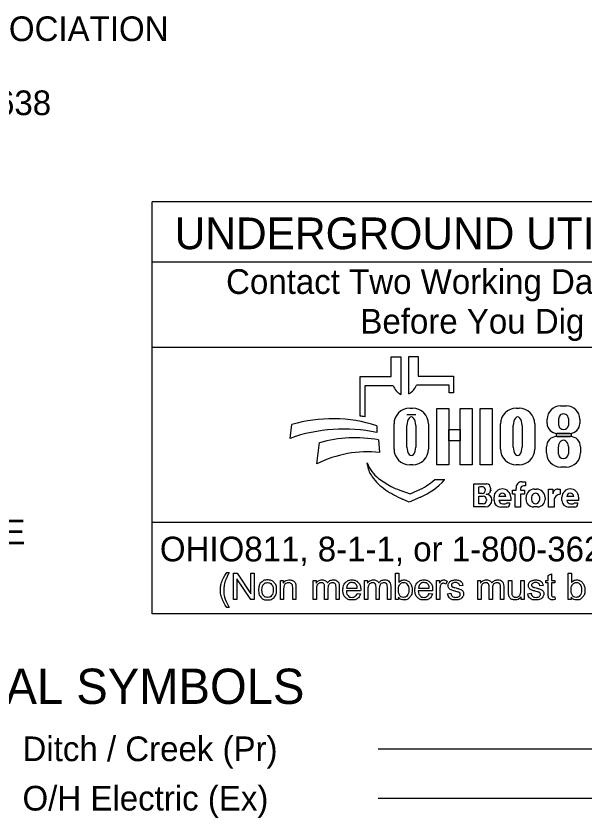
# Model space of a CAD drawing. Extents: x 0 to 34, y 0 to 22.
# Drawn here: x 7.923 to 11.147, y 5.615 to 10.163 of the extents above; entities that cross this region are included whole.
import ezdxf

# ---------------------------------------------------------------- set-up
doc = ezdxf.new("R2010")
doc.units = 0
for name, color, linetype in [('SH_Data', 7, 'Continuous'), ('SH_Text', 7, 'Continuous'), ('UT_X_Overhead_Electric', 7, 'Continuous')]:
    doc.layers.add(name, color=color, linetype=linetype)

msp = doc.modelspace()

# ---------------------------------------------------------------- linework, layer by layer
at = {"layer": 'SH_Data'}
for p, q in [((8.6934, 6.7724), (8.6934, 9.1099)), ((12.9434, 9.1099), (8.6934, 9.1099)), ((8.6934, 8.7683), (12.9434, 8.7683)), ((8.6934, 8.2849), (12.9434, 8.2849)), ((12.9434, 7.2902), (8.6934, 7.2902)), ((12.9434, 6.7724), (8.6934, 6.7724))]:
    msp.add_line(p, q, dxfattribs=at)
at = {"layer": 'SH_Text'}
for p, q in [((10.1488, 8.0196), (10.1488, 8.2317)), ((10.1488, 8.2317), (10.2024, 8.2317)), ((10.2024, 8.2317), (10.2024, 8.1202)), ((10.0495, 8.1179), (10.0495, 8.2294)), ((10.0495, 8.2294), (10.1031, 8.2294)), ((10.1031, 8.2294), (10.1031, 8.0173)), ((9.8735, 7.894), (9.8735, 8.1179)), ((9.8735, 8.1179), (10.0495, 8.1179)), ((10.2024, 8.1202), (10.4017, 8.1202)), ((10.4017, 8.1202), (10.4017, 8.0264)), ((9.8987, 8.0664), (9.8987, 7.8896)), ((10.0599, 8.0664), (9.8987, 8.0664)), ((10.3784, 8.0687), (10.192, 8.0687)), ((10.3784, 8.0264), (10.3784, 8.0687)), ((10.4017, 8.0264), (10.3784, 8.0264)), ((10.1544, 7.9387), (10.171, 7.9387)), ((10.7575, 7.9387), (10.774, 7.9387)), ((11.009, 7.9527), (11.0418, 7.9527)), ((10.1877, 7.9017), (10.1379, 7.9017)), ((10.9327, 7.8521), (10.9327, 7.8764)), ((10.9989, 7.8407), (10.9989, 7.88)), ((11.053, 7.88), (11.053, 7.8407)), ((11.1181, 7.8764), (11.1181, 7.8521)), ((9.4761, 7.7677), (9.4855, 7.8458)), ((9.9668, 7.8393), (9.9668, 7.8005)), ((10.065, 7.7072), (10.065, 7.8492)), ((10.1379, 7.7186), (10.1379, 7.8409)), ((10.1877, 7.8409), (10.1877, 7.7186)), ((10.2604, 7.8492), (10.2604, 7.7072)), ((10.668, 7.7072), (10.668, 7.8492)), ((10.7409, 7.7186), (10.7409, 7.8409)), ((10.7907, 7.8409), (10.7907, 7.7186)), ((10.8635, 7.8492), (10.8635, 7.7072)), ((10.9869, 7.7778), (11.0642, 7.7778)), ((11.0621, 7.7961), (10.9887, 7.7961)), ((9.628, 7.6231), (9.6426, 7.7433)), ((9.9768, 7.7587), (9.983, 7.6878)), ((10.929, 7.6859), (10.929, 7.7199)), ((10.9965, 7.6799), (10.9965, 7.7208)), ((11.0534, 7.7208), (11.0534, 7.6799)), ((11.1221, 7.7199), (11.1221, 7.6859)), ((9.9156, 7.6102), (9.9126, 7.6282)), ((10.171, 7.6177), (10.1544, 7.6177)), ((10.774, 7.6177), (10.7575, 7.6177)), ((11.0412, 7.6049), (11.01, 7.6049)), ((10.2959, 7.5344), (10.3534, 7.5344)), ((10.5172, 7.3786), (10.5172, 7.5093)), ((10.5172, 7.5093), (10.5884, 7.5093)), ((10.7898, 7.5221), (10.8093, 7.5221)), ((10.8093, 7.5221), (10.8093, 7.4992)), ((10.0975, 7.474), (10.1569, 7.4535)), ((10.1569, 7.4535), (10.198, 7.4713)), ((10.5452, 7.4559), (10.5452, 7.4928)), ((10.5704, 7.4928), (10.5491, 7.4928)), ((10.6122, 7.4856), (10.6122, 7.4777)), ((10.7372, 7.4508), (10.7372, 7.4737)), ((10.7372, 7.4737), (10.7565, 7.4737)), ((10.7565, 7.4737), (10.7565, 7.4842)), ((10.7826, 7.4822), (10.7826, 7.4737)), ((10.7826, 7.4737), (10.8042, 7.4737)), ((10.8093, 7.4987), (10.7991, 7.4987)), ((10.8042, 7.4737), (10.8042, 7.4508)), ((10.861, 7.4803), (10.8732, 7.4803)), ((10.9413, 7.3774), (10.9413, 7.4801)), ((10.9413, 7.4801), (10.9658, 7.4801)), ((10.9658, 7.4801), (10.9658, 7.4532)), ((10.9931, 7.4801), (11.007, 7.4801)), ((11.007, 7.4801), (11.007, 7.4505)), ((10.1509, 7.4065), (10.1136, 7.4229)), ((10.2142, 7.4339), (10.1509, 7.4065)), ((10.5646, 7.4559), (10.5452, 7.4559)), ((10.5452, 7.3964), (10.5452, 7.4393)), ((10.5452, 7.4393), (10.5707, 7.4393)), ((10.5889, 7.4212), (10.5889, 7.4148)), ((10.6202, 7.4183), (10.6202, 7.4179)), ((10.6318, 7.4154), (10.6318, 7.4338)), ((10.6984, 7.4378), (10.6598, 7.4378)), ((10.7263, 7.4161), (10.6599, 7.4161)), ((10.7263, 7.4338), (10.7263, 7.4161)), ((10.7521, 7.4508), (10.7372, 7.4508)), ((10.7521, 7.3774), (10.7521, 7.4508)), ((10.8042, 7.4508), (10.7826, 7.4508)), ((10.7826, 7.4508), (10.7826, 7.3774)), ((10.8132, 7.4217), (10.8132, 7.4325)), ((10.921, 7.4325), (10.921, 7.4217)), ((10.9718, 7.4155), (10.9718, 7.3774)), ((11.0167, 7.4154), (11.0167, 7.4338)), ((11.0833, 7.4378), (11.0448, 7.4378)), ((11.1112, 7.4161), (11.0448, 7.4161)), ((11.1112, 7.4338), (11.1112, 7.4161)), ((10.5809, 7.3786), (10.5172, 7.3786)), ((10.5705, 7.3964), (10.5452, 7.3964)), ((10.7051, 7.3774), (10.6697, 7.3774)), ((10.6808, 7.3969), (10.6949, 7.3969)), ((10.7035, 7.4025), (10.7204, 7.4025)), ((10.7204, 7.4025), (10.7204, 7.3926)), ((10.7826, 7.3774), (10.7521, 7.3774)), ((10.8782, 7.3789), (10.856, 7.3789)), ((10.9718, 7.3774), (10.9413, 7.3774)), ((11.0901, 7.3774), (11.0547, 7.3774)), ((11.0657, 7.3969), (11.0799, 7.3969)), ((11.0884, 7.4025), (11.1053, 7.4025)), ((11.1053, 7.4025), (11.1053, 7.3926)), ((9.9753, 6.0072), (13.8753, 6.0072))]:
    msp.add_line(p, q, dxfattribs=at)
for points in [[(10.3069, 7.9376), (10.3748, 7.9376), (10.3748, 7.6177), (10.3069, 7.6177)], [(10.439, 7.9376), (10.507, 7.9376), (10.507, 7.6177), (10.439, 7.6177)], [(10.5523, 7.9376), (10.6211, 7.9376), (10.6211, 7.6177), (10.5523, 7.6177)], [(10.3748, 7.8177), (10.439, 7.8177), (10.439, 7.7538), (10.3748, 7.7538)], [(10.9866, 7.7961), (11.0682, 7.7961), (11.0682, 7.7776), (10.9866, 7.7776)]]:
    msp.add_lwpolyline(points, close=True, dxfattribs=at)
for points in [[(9.118, 7.0062), (9.1312, 7.0062)], [(9.1548, 6.8535), (9.1548, 7.0036), (9.1751, 7.0036), (9.2541, 6.8857), (9.2541, 7.0036), (9.2731, 7.0036), (9.2731, 6.8535), (9.2528, 6.8535), (9.1738, 6.9714), (9.1738, 6.8535), (9.1548, 6.8535)], [(10.0902, 6.8535), (10.0732, 6.8535), (10.0732, 7.0036), (10.0916, 7.0036), (10.0916, 6.9501)], [(11.0693, 6.8535), (11.0523, 6.8535), (11.0523, 7.0036), (11.0707, 7.0036), (11.0707, 6.9501)], [(9.4207, 6.8535), (9.4207, 6.9623), (9.4373, 6.9623), (9.4373, 6.9469)], [(9.6072, 6.8535), (9.6072, 6.9623), (9.6236, 6.9623), (9.6236, 6.947)], [(9.8985, 6.8535), (9.8985, 6.9623), (9.915, 6.9623), (9.915, 6.947)], [(10.3063, 6.8535), (10.3063, 6.9623), (10.3229, 6.9623), (10.3229, 6.9458)], [(10.3654, 6.9588), (10.3589, 6.9418)], [(10.5395, 6.8535), (10.5395, 6.9623), (10.556, 6.9623), (10.556, 6.947)], [(10.7138, 6.8949), (10.7138, 6.9623), (10.7323, 6.9623), (10.7323, 6.902)], [(10.7835, 6.9041), (10.7835, 6.9623), (10.802, 6.9623), (10.802, 6.8535), (10.7855, 6.8535)], [(10.9392, 6.8853), (10.9392, 6.948), (10.9256, 6.948), (10.9256, 6.9623), (10.9392, 6.9623), (10.9392, 6.9893), (10.9576, 7.0003), (10.9576, 6.9623), (10.976, 6.9623), (10.976, 6.948), (10.9576, 6.948), (10.9576, 6.8843)], [(9.4392, 6.9129), (9.4392, 6.8535), (9.4207, 6.8535)], [(9.5091, 6.9204), (9.5091, 6.8535), (9.4907, 6.8535), (9.4907, 6.9196)], [(9.6902, 6.9167), (9.6902, 6.8535), (9.6718, 6.8535), (9.6718, 6.9241)], [(9.7547, 6.9282), (9.7547, 6.8535), (9.7362, 6.8535), (9.7362, 6.922)], [(9.7958, 6.9183), (9.8565, 6.9183)], [(9.9816, 6.9167), (9.9816, 6.8535), (9.9632, 6.8535), (9.9632, 6.9241)], [(10.046, 6.9282), (10.046, 6.8535), (10.0276, 6.8535), (10.0276, 6.922)], [(10.2038, 6.9183), (10.2645, 6.9183)], [(10.4553, 6.9342), (10.4372, 6.9318)], [(10.6226, 6.9167), (10.6226, 6.8535), (10.6042, 6.8535), (10.6042, 6.9241)], [(10.687, 6.9282), (10.687, 6.8535), (10.6686, 6.8535), (10.6686, 6.922)], [(10.9099, 6.9342), (10.8918, 6.9318)], [(9.6256, 6.9099), (9.6256, 6.8535), (9.6072, 6.8535)], [(9.8759, 6.9032), (9.7947, 6.9032)], [(9.8563, 6.8886), (9.8754, 6.8862)], [(9.917, 6.9099), (9.917, 6.8535), (9.8985, 6.8535)], [(10.0902, 6.8671), (10.0902, 6.8535)], [(10.2839, 6.9032), (10.2027, 6.9032)], [(10.2643, 6.8886), (10.2834, 6.8862)], [(10.3247, 6.9105), (10.3247, 6.8535), (10.3063, 6.8535)], [(10.3689, 6.886), (10.3871, 6.8889)], [(10.558, 6.9099), (10.558, 6.8535), (10.5395, 6.8535)], [(10.7855, 6.8535), (10.7855, 6.8696)], [(10.8235, 6.886), (10.8417, 6.8889)], [(10.976, 6.8699), (10.9787, 6.8536)], [(11.0693, 6.8671), (11.0693, 6.8535)], [(9.1312, 6.8093), (9.118, 6.8093)]]:
    msp.add_lwpolyline(points, dxfattribs=at)
for centre, radius, start, end in [((10.1512, 8.1032), 0.0985, 201.9296, 240.7469), ((10.1006, 8.1055), 0.0985, 299.2531, 338.0704), ((10.1544, 7.8492), 0.0895, 90, 180), ((10.171, 7.8492), 0.0895, 0, 90), ((10.7575, 7.8492), 0.0895, 90, 180), ((10.774, 7.8492), 0.0895, 0, 90), ((11.009, 7.8764), 0.0763, 90, 180), ((11.0418, 7.8764), 0.0763, 0, 90), ((9.7156, 7.0597), 0.8191, 72.1402, 106.3144), ((9.7454, 7.085), 0.8191, 79.2074, 81.0007), ((10.9887, 7.8521), 0.056, 180, 270), ((11.0621, 7.8521), 0.056, 270, 0), ((9.7787, 6.9286), 0.8919, 77.8238, 109.8274), ((10.9869, 7.7199), 0.0579, 90, 180), ((11.0642, 7.7199), 0.0579, 0, 90), ((9.8426, 7.0389), 0.7322, 79.44, 105.8467), ((9.9146, 7.0557), 0.6357, 83.8248, 116.8021), ((10.1544, 7.7072), 0.0895, 180, 270), ((10.171, 7.7072), 0.0895, 270, 0), ((10.7575, 7.7072), 0.0895, 180, 270), ((10.774, 7.7072), 0.0895, 270, 0), ((11.01, 7.6859), 0.081, 180, 270), ((11.0412, 7.6859), 0.081, 270, 0), ((10.1, 7.7003), 0.2008, 201.0457, 232.5314), ((10.0569, 7.6344), 0.1433, 189.6817, 216.0884), ((10.1906, 7.7318), 0.3088, 216.0884, 235.7167), ((10.2925, 7.9515), 0.5173, 232.5314, 241.794), ((10.0546, 7.8018), 0.3602, 293.4582, 312.0712), ((10.0546, 7.8018), 0.401, 293.4582, 317.8286), ((10.5884, 7.4856), 0.0238, 0, 90), ((10.7898, 7.4886), 0.0335, 90, 187.5187), ((10.3571, 7.976), 0.6044, 235.7167, 246.2325), ((10.2073, 7.7927), 0.3371, 241.794, 250.9821), ((10.5646, 7.4746), 0.0187, 270, 2.0582), ((10.5665, 7.4759), 0.0169, 357.8325, 90), ((10.588, 7.4749), 0.0243, 270, 6.6529), ((10.5986, 7.4734), 0.0175, 347.4023, 0), ((10.679, 7.4338), 0.0473, 0, 180), ((10.7991, 7.4822), 0.0165, 90, 180), ((10.861, 7.4325), 0.0478, 90, 180), ((10.8732, 7.4325), 0.0478, 0, 90), ((10.9927, 7.4532), 0.0269, 89.2449, 180), ((11.064, 7.4338), 0.0473, 0, 180), ((10.5705, 7.4148), 0.0184, 270, 0), ((10.5707, 7.4212), 0.0181, 0, 90), ((10.5809, 7.4179), 0.0393, 270, 0), ((10.5881, 7.4185), 0.0321, 4.0748, 90), ((10.5873, 7.4183), 0.033, 0, 11.7502), ((10.6697, 7.4154), 0.038, 180, 270), ((10.6791, 7.4368), 0.0193, 2.9632, 177.0368), ((10.6808, 7.4179), 0.021, 184.827, 270), ((10.856, 7.4217), 0.0428, 180, 270), ((10.8782, 7.4217), 0.0428, 270, 0), ((11.0067, 7.4155), 0.0349, 89.6033, 180), ((11.0547, 7.4154), 0.038, 180, 270), ((11.064, 7.4368), 0.0193, 2.9632, 177.0368), ((11.0657, 7.4179), 0.021, 184.827, 270), ((10.6949, 7.4063), 0.00938, 270, 335.9979), ((10.7051, 7.3926), 0.0152, 270, 0), ((11.0799, 7.4063), 0.00938, 270, 335.9979), ((11.0901, 7.3926), 0.0152, 270, 0)]:
    msp.add_arc(centre, radius, start, end, dxfattribs=at)
for centre, major_axis, ratio, start_param, end_param in [((10.1628, 7.8409), (0, 0.0484), 0.514403, 4.712389, 7.853982), ((10.7658, 7.8409), (0, 0.0484), 0.514403, 4.712389, 7.853982), ((11.0259, 7.88), (0.0271, 0), 0.969373, 0, 3.141593), ((11.0259, 7.8407), (0.0271, 0), 0.818453, 3.141593, 6.283185), ((11.0249, 7.7208), (0, 0.0358), 0.794529, 4.712389, 7.853982), ((10.1628, 7.7186), (0, 0.0484), 0.514403, 1.570796, 4.712389), ((10.7658, 7.7186), (0, 0.0484), 0.514403, 1.570796, 4.712389), ((11.0249, 7.6799), (0.0284, 0), 0.959837, 3.141593, 6.283185), ((10.8676, 7.4271), (0, 0.029), 0.832186, 4.712389, 7.853982), ((10.8676, 7.4271), (0, 0.0302), 0.797287, 1.570796, 4.712389)]:
    msp.add_ellipse(centre, major_axis=major_axis, ratio=ratio, start_param=start_param, end_param=end_param, dxfattribs=at)
for points in [[(9.118, 6.8093), (9.1028, 6.8286), (9.0922, 6.8544), (9.0816, 6.8802), (9.0816, 6.9078), (9.0816, 6.9322), (9.0895, 6.9545), (9.0988, 6.9805), (9.118, 7.0062)], [(9.1312, 7.0062), (9.1188, 6.9849), (9.1149, 6.9757), (9.1086, 6.9616), (9.105, 6.9462), (9.1006, 6.9271), (9.1006, 6.9077), (9.1006, 6.8585), (9.1312, 6.8093)], [(9.2973, 6.9079), (9.2973, 6.9381), (9.314, 6.9526), (9.3281, 6.9647), (9.3482, 6.9647), (9.3707, 6.9647), (9.3849, 6.95), (9.3991, 6.9353), (9.3991, 6.9094), (9.3991, 6.8885), (9.3928, 6.8764), (9.3865, 6.8644), (9.3745, 6.8577), (9.3625, 6.8511), (9.3482, 6.8511), (9.3254, 6.8511), (9.3113, 6.8657), (9.2973, 6.8804), (9.2973, 6.9079)], [(9.4373, 6.9469), (9.4493, 6.9647), (9.4719, 6.9647), (9.4818, 6.9647), (9.49, 6.9612), (9.4982, 6.9577), (9.5023, 6.9519), (9.5064, 6.9462), (9.5081, 6.9383), (9.5091, 6.9332), (9.5091, 6.9204)], [(9.6236, 6.947), (9.6288, 6.955), (9.6373, 6.9599), (9.6458, 6.9647), (9.6566, 6.9647), (9.6687, 6.9647), (9.6765, 6.9597), (9.6842, 6.9547), (9.6874, 6.9456), (9.7003, 6.9647), (9.721, 6.9647), (9.7372, 6.9647), (9.746, 6.9558), (9.7547, 6.9468), (9.7547, 6.9282)], [(9.8754, 6.8862), (9.8709, 6.8695), (9.8587, 6.8603), (9.8465, 6.8511), (9.8276, 6.8511), (9.8037, 6.8511), (9.7897, 6.8658), (9.7757, 6.8805), (9.7757, 6.907), (9.7757, 6.9344), (9.7899, 6.9496), (9.804, 6.9647), (9.8265, 6.9647), (9.8484, 6.9647), (9.8622, 6.9499), (9.876, 6.935), (9.876, 6.9081), (9.876, 6.9064), (9.8759, 6.9032)], [(9.915, 6.947), (9.9201, 6.955), (9.9286, 6.9599), (9.9371, 6.9647), (9.948, 6.9647), (9.9601, 6.9647), (9.9678, 6.9597), (9.9756, 6.9547), (9.9787, 6.9456), (9.9917, 6.9647), (10.0124, 6.9647), (10.0286, 6.9647), (10.0373, 6.9558), (10.046, 6.9468), (10.046, 6.9282)], [(10.0916, 6.9501), (10.1033, 6.9647), (10.1214, 6.9647), (10.1314, 6.9647), (10.1404, 6.9607), (10.1494, 6.9566), (10.1552, 6.9493), (10.1609, 6.942), (10.1642, 6.9317), (10.1675, 6.9213), (10.1675, 6.9095), (10.1675, 6.8816), (10.1537, 6.8663), (10.1398, 6.8511), (10.1205, 6.8511), (10.1012, 6.8511), (10.0902, 6.8671)], [(10.2834, 6.8862), (10.2789, 6.8695), (10.2667, 6.8603), (10.2545, 6.8511), (10.2356, 6.8511), (10.2117, 6.8511), (10.1977, 6.8658), (10.1837, 6.8805), (10.1837, 6.907), (10.1837, 6.9344), (10.1979, 6.9496), (10.212, 6.9647), (10.2345, 6.9647), (10.2563, 6.9647), (10.2702, 6.9499), (10.284, 6.935), (10.284, 6.9081), (10.284, 6.9064), (10.2839, 6.9032)], [(10.3229, 6.9458), (10.3292, 6.9574), (10.3346, 6.9611), (10.34, 6.9647), (10.3464, 6.9647), (10.3557, 6.9647), (10.3654, 6.9588)], [(10.3871, 6.8889), (10.3886, 6.8779), (10.3957, 6.872), (10.4027, 6.8662), (10.4154, 6.8662), (10.4281, 6.8662), (10.4343, 6.8714), (10.4404, 6.8766), (10.4404, 6.8835), (10.4404, 6.8898), (10.435, 6.8934), (10.4312, 6.8958), (10.4161, 6.8996), (10.3958, 6.9048), (10.388, 6.9085), (10.3801, 6.9122), (10.3761, 6.9188), (10.372, 6.9254), (10.372, 6.9334), (10.372, 6.9407), (10.3753, 6.9469), (10.3787, 6.9531), (10.3844, 6.9572), (10.3887, 6.9603), (10.3962, 6.9625), (10.4036, 6.9647), (10.4121, 6.9647), (10.4249, 6.9647), (10.4346, 6.961), (10.4443, 6.9573), (10.449, 6.951), (10.4536, 6.9447), (10.4553, 6.9342)], [(10.556, 6.947), (10.5611, 6.955), (10.5696, 6.9599), (10.5781, 6.9647), (10.589, 6.9647), (10.6011, 6.9647), (10.6088, 6.9597), (10.6166, 6.9547), (10.6197, 6.9456), (10.6327, 6.9647), (10.6534, 6.9647), (10.6696, 6.9647), (10.6783, 6.9558), (10.687, 6.9468), (10.687, 6.9282)], [(10.8417, 6.8889), (10.8432, 6.8779), (10.8503, 6.872), (10.8573, 6.8662), (10.8699, 6.8662), (10.8827, 6.8662), (10.8888, 6.8714), (10.895, 6.8766), (10.895, 6.8835), (10.895, 6.8898), (10.8896, 6.8934), (10.8858, 6.8958), (10.8707, 6.8996), (10.8504, 6.9048), (10.8425, 6.9085), (10.8347, 6.9122), (10.8306, 6.9188), (10.8266, 6.9254), (10.8266, 6.9334), (10.8266, 6.9407), (10.8299, 6.9469), (10.8332, 6.9531), (10.839, 6.9572), (10.8433, 6.9603), (10.8507, 6.9625), (10.8582, 6.9647), (10.8667, 6.9647), (10.8795, 6.9647), (10.8892, 6.961), (10.8989, 6.9573), (10.9035, 6.951), (10.9081, 6.9447), (10.9099, 6.9342)], [(11.0707, 6.9501), (11.0824, 6.9647), (11.1005, 6.9647), (11.1105, 6.9647), (11.1195, 6.9607), (11.1284, 6.9566), (11.1342, 6.9493), (11.14, 6.942), (11.1433, 6.9317), (11.1466, 6.9213), (11.1466, 6.9095), (11.1466, 6.8816), (11.1327, 6.8663), (11.1189, 6.8511), (11.0995, 6.8511), (11.0803, 6.8511), (11.0693, 6.8671)], [(9.3163, 6.9079), (9.3163, 6.887), (9.3254, 6.8766), (9.3344, 6.8662), (9.3482, 6.8662), (9.3619, 6.8662), (9.371, 6.8766), (9.3801, 6.8871), (9.3801, 6.9085), (9.3801, 6.9287), (9.371, 6.9391), (9.3618, 6.9495), (9.3482, 6.9495), (9.3344, 6.9495), (9.3254, 6.9392), (9.3163, 6.9288), (9.3163, 6.9079)], [(9.4907, 6.9196), (9.4907, 6.9309), (9.4885, 6.9365), (9.4864, 6.9421), (9.4809, 6.9454), (9.4754, 6.9487), (9.468, 6.9487), (9.4563, 6.9487), (9.4477, 6.9412), (9.4392, 6.9338), (9.4392, 6.9129)], [(9.6718, 6.9241), (9.6718, 6.9364), (9.6673, 6.9426), (9.6628, 6.9487), (9.6525, 6.9487), (9.6448, 6.9487), (9.6381, 6.9446), (9.6315, 6.9405), (9.6286, 6.9326), (9.6256, 6.9248), (9.6256, 6.9099)], [(9.7362, 6.922), (9.7362, 6.933), (9.7345, 6.9379), (9.7327, 6.9428), (9.7279, 6.9457), (9.7232, 6.9487), (9.7169, 6.9487), (9.7054, 6.9487), (9.6978, 6.9411), (9.6902, 6.9335), (9.6902, 6.9167)], [(9.8565, 6.9183), (9.8553, 6.932), (9.8496, 6.9389), (9.8408, 6.9496), (9.8267, 6.9496), (9.814, 6.9496), (9.8054, 6.9411), (9.7967, 6.9326), (9.7958, 6.9183)], [(9.9632, 6.9241), (9.9632, 6.9364), (9.9587, 6.9426), (9.9542, 6.9487), (9.9439, 6.9487), (9.9361, 6.9487), (9.9295, 6.9446), (9.9229, 6.9405), (9.9199, 6.9326), (9.917, 6.9248), (9.917, 6.9099)], [(10.0276, 6.922), (10.0276, 6.933), (10.0258, 6.9379), (10.024, 6.9428), (10.0193, 6.9457), (10.0146, 6.9487), (10.0083, 6.9487), (9.9968, 6.9487), (9.9892, 6.9411), (9.9816, 6.9335), (9.9816, 6.9167)], [(10.09, 6.9087), (10.09, 6.8892), (10.0953, 6.8804), (10.104, 6.8662), (10.1188, 6.8662), (10.1309, 6.8662), (10.1397, 6.8767), (10.1485, 6.8872), (10.1485, 6.908), (10.1485, 6.9293), (10.1401, 6.9395), (10.1316, 6.9496), (10.1197, 6.9496), (10.1076, 6.9496), (10.0988, 6.9391), (10.09, 6.9286), (10.09, 6.9087)], [(10.2645, 6.9183), (10.2633, 6.932), (10.2576, 6.9389), (10.2488, 6.9496), (10.2347, 6.9496), (10.222, 6.9496), (10.2134, 6.9411), (10.2047, 6.9326), (10.2038, 6.9183)], [(10.3589, 6.9418), (10.3522, 6.9457), (10.3455, 6.9457), (10.3394, 6.9457), (10.3346, 6.9421), (10.3299, 6.9385), (10.3278, 6.932), (10.3247, 6.9222), (10.3247, 6.9105)], [(10.4372, 6.9318), (10.436, 6.9402), (10.4301, 6.9449), (10.4242, 6.9496), (10.4134, 6.9496), (10.4007, 6.9496), (10.3953, 6.9454), (10.3899, 6.9412), (10.3899, 6.9356), (10.3899, 6.932), (10.3921, 6.9291), (10.3944, 6.9261), (10.3992, 6.9242), (10.402, 6.9232), (10.4155, 6.9195), (10.4351, 6.9142), (10.4428, 6.9109), (10.4506, 6.9076), (10.455, 6.9012), (10.4594, 6.8949), (10.4594, 6.8855), (10.4594, 6.8763), (10.454, 6.8681), (10.4487, 6.86), (10.4385, 6.8555), (10.4283, 6.8511), (10.4155, 6.8511), (10.3943, 6.8511), (10.3831, 6.8599), (10.372, 6.8687), (10.3689, 6.886)], [(10.6042, 6.9241), (10.6042, 6.9364), (10.5997, 6.9426), (10.5952, 6.9487), (10.5849, 6.9487), (10.5771, 6.9487), (10.5705, 6.9446), (10.5639, 6.9405), (10.5609, 6.9326), (10.558, 6.9248), (10.558, 6.9099)], [(10.6686, 6.922), (10.6686, 6.933), (10.6668, 6.9379), (10.665, 6.9428), (10.6603, 6.9457), (10.6556, 6.9487), (10.6493, 6.9487), (10.6378, 6.9487), (10.6302, 6.9411), (10.6226, 6.9335), (10.6226, 6.9167)], [(10.8918, 6.9318), (10.8906, 6.9402), (10.8847, 6.9449), (10.8788, 6.9496), (10.868, 6.9496), (10.8553, 6.9496), (10.8499, 6.9454), (10.8444, 6.9412), (10.8444, 6.9356), (10.8444, 6.932), (10.8467, 6.9291), (10.8489, 6.9261), (10.8538, 6.9242), (10.8565, 6.9232), (10.8701, 6.9195), (10.8897, 6.9142), (10.8974, 6.9109), (10.9052, 6.9076), (10.9096, 6.9012), (10.914, 6.8949), (10.914, 6.8855), (10.914, 6.8763), (10.9086, 6.8681), (10.9032, 6.86), (10.8931, 6.8555), (10.8829, 6.8511), (10.8701, 6.8511), (10.8488, 6.8511), (10.8377, 6.8599), (10.8266, 6.8687), (10.8235, 6.886)], [(11.0691, 6.9087), (11.0691, 6.8892), (11.0744, 6.8804), (11.0831, 6.8662), (11.0979, 6.8662), (11.11, 6.8662), (11.1188, 6.8767), (11.1276, 6.8872), (11.1276, 6.908), (11.1276, 6.9293), (11.1191, 6.9395), (11.1107, 6.9496), (11.0987, 6.9496), (11.0867, 6.9496), (11.0779, 6.9391), (11.0691, 6.9286), (11.0691, 6.9087)], [(9.7947, 6.9032), (9.7958, 6.8852), (9.8049, 6.8757), (9.814, 6.8662), (9.8276, 6.8662), (9.8378, 6.8662), (9.845, 6.8715), (9.8521, 6.8769), (9.8563, 6.8886)], [(10.2027, 6.9032), (10.2038, 6.8852), (10.2129, 6.8757), (10.222, 6.8662), (10.2356, 6.8662), (10.2458, 6.8662), (10.253, 6.8715), (10.2601, 6.8769), (10.2643, 6.8886)], [(10.7855, 6.8696), (10.7728, 6.8511), (10.751, 6.8511), (10.7414, 6.8511), (10.733, 6.8548), (10.7247, 6.8585), (10.7206, 6.864), (10.7166, 6.8696), (10.715, 6.8777), (10.7138, 6.8831), (10.7138, 6.8949)], [(10.7323, 6.902), (10.7323, 6.8876), (10.7334, 6.8826), (10.7351, 6.8753), (10.7408, 6.8711), (10.7464, 6.867), (10.7547, 6.867), (10.763, 6.867), (10.7702, 6.8712), (10.7775, 6.8755), (10.7805, 6.8828), (10.7835, 6.8901), (10.7835, 6.9041)], [(10.9787, 6.8536), (10.9709, 6.852), (10.9648, 6.852), (10.9547, 6.852), (10.9492, 6.8552), (10.9437, 6.8584), (10.9414, 6.8635), (10.9392, 6.8687), (10.9392, 6.8853)], [(10.9576, 6.8843), (10.9576, 6.8764), (10.9586, 6.8741), (10.9595, 6.8718), (10.9617, 6.8705), (10.9639, 6.8692), (10.968, 6.8692), (10.971, 6.8692), (10.976, 6.8699)]]:
    msp.add_open_spline(points, degree=3, dxfattribs=at)
at = {"layer": 'UT_X_Overhead_Electric'}
msp.add_line((9.9753, 5.7272), (13.8753, 5.7272), dxfattribs=at)

# ---------------------------------------------------------------- texts
at = {"layer": 'SH_Text'}
for s, height, p in [('HECLA WATER ASSOCIATION', 0.14, (6.1031, 10.0205)), ('IRONTON, OHIO 45638', 0.14, (6.1031, 9.6005)), ('UNDERGROUND UTILITIES', 0.18, (8.8216, 8.8402)), ('Contact Two Working Days', 0.14, (9.1131, 8.5867)), ('Before You Dig', 0.14, (9.8742, 8.3617)), ('THE LOCATION OF THE UNDERGROUND UTILITIES SHOWN ON THE ', 0.14, (1.8488, 7.1668)), ('OHIO811, 8-1-1, or 1-800-362-2764', 0.14, (8.7379, 7.0702)), ('CONVENTIONAL SYMBOLS', 0.2, (6.0795, 6.2618)), ('Ditch / Creek (Pr)', 0.14, (7.9591, 5.9372)), ('O/H Electric (Ex)', 0.14, (7.9591, 5.6572))]:
    msp.add_text(s, height=height, dxfattribs=at).set_placement(p)

doc.saveas('drawing.dxf')
